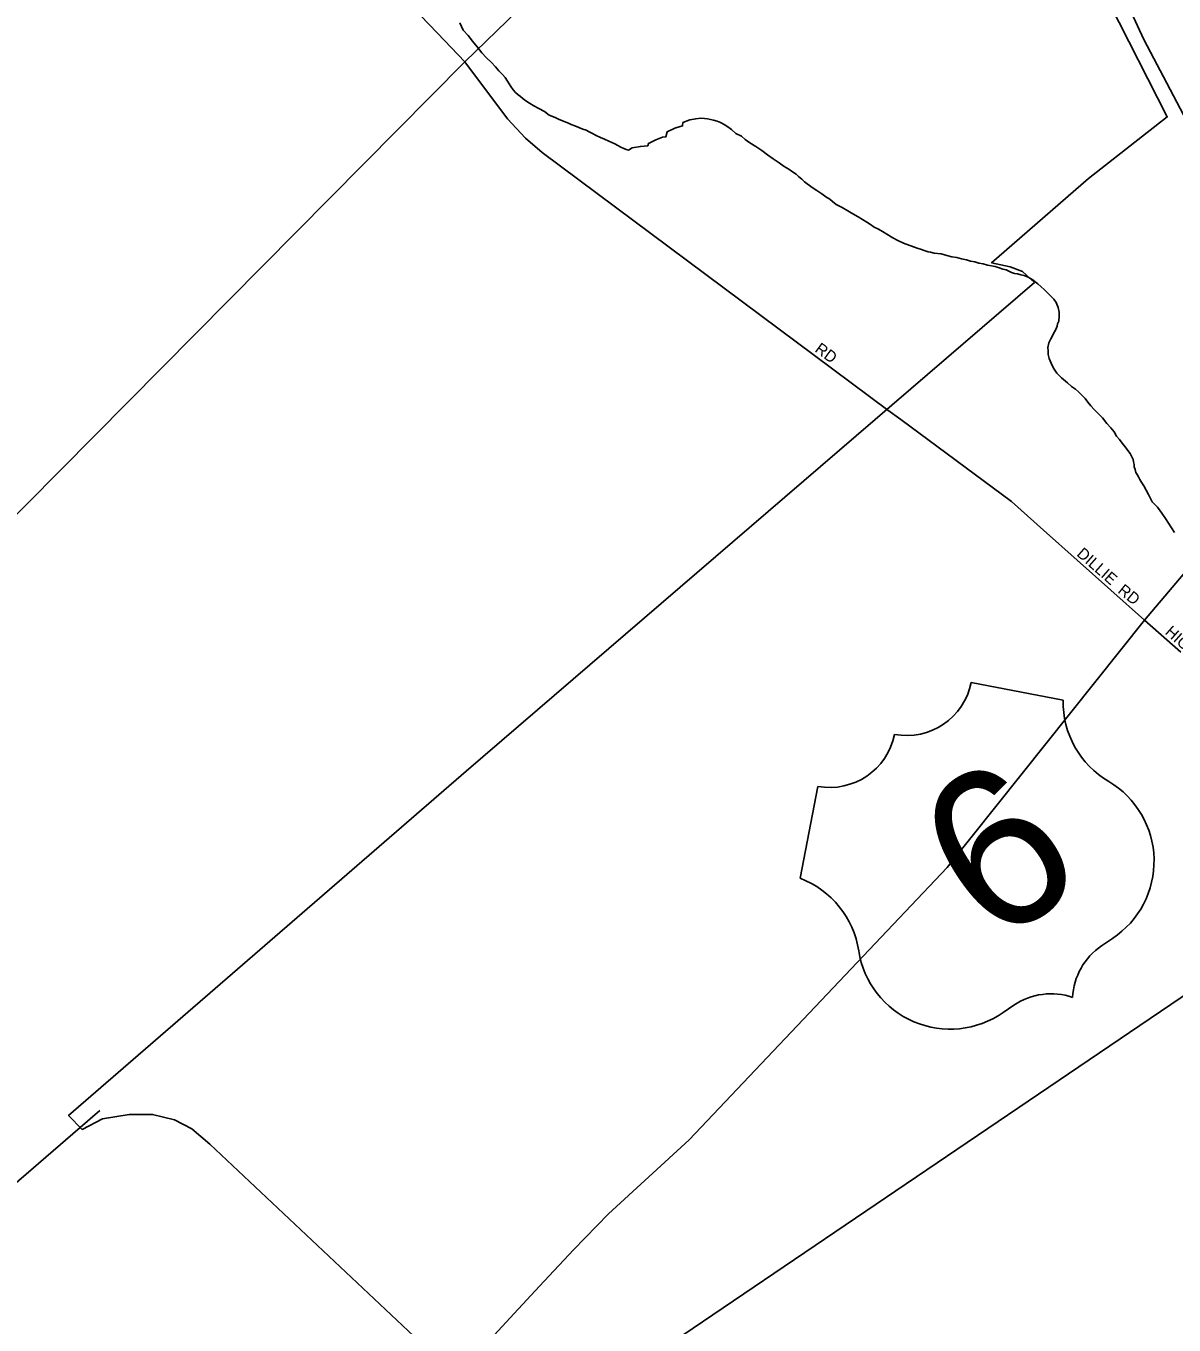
# Model space of a CAD drawing. Extents: x 2139079 to 2262683, y 1235796 to 1334992.
# Drawn here: x 2227269 to 2232304, y 1297941 to 1303635 of the extents above; entities that cross this region are included whole.
import ezdxf

# ---------------------------------------------------------------- set-up
doc = ezdxf.new("R2010")
doc.units = 0
for name, color, linetype in [('GM_X_City_Street', 7, 'Continuous'), ('GM_X_City_Street_Text', 7, 'Continuous'), ('GM_X_Interstate_Route', 7, 'Continuous'), ('GM_X_Minor_River', 7, 'Continuous'), ('GM_X_Rail_Line', 7, 'Continuous'), ('GM_X_US_Location', 7, 'Continuous'), ('GM_X_US_Route', 7, 'Continuous'), ('GM_X_US_Shield', 7, 'Continuous')]:
    doc.layers.add(name, color=color, linetype=linetype)

msp = doc.modelspace()

# ---------------------------------------------------------------- linework, layer by layer
at = {"layer": 'GM_X_City_Street'}
for points in [[(2229193.8, 1303478.3), (2229473.2, 1303749.8), (2230411, 1304512.8), (2231077.9, 1305045.6)], [(2233088.2, 1301840), (2233073.5, 1301864.9), (2233067.4, 1301875.3), (2232171, 1303576.2), (2232079.2, 1303776.5), (2232018.5, 1303862.8), (2231965.8, 1303917.1), (2231913.1, 1303961.8), (2231842.8, 1304001.7), (2231723.7, 1304043.3), (2231524.1, 1304095.9), (2230915.6, 1304246.1), (2230871.3, 1304269.6)], [(2229073.7, 1303604), (2228926.2, 1303758.5), (2228706.1, 1303984), (2228677, 1304023.6), (2228653.9, 1304065.1), (2228645, 1304093.7), (2228640.1, 1304120.2), (2228638.6, 1304139)], [(2231049, 1301951.7), (2229532.4, 1303081.2), (2229459.8, 1303142.9), (2229380.3, 1303227.8), (2229193.8, 1303478.3), (2229073.7, 1303604)], [(2224021.1, 1298258), (2229193.8, 1303478.3)], [(2231731.9, 1301425.2), (2231591.7, 1301550.4), (2231105.2, 1301909.9), (2231049, 1301951.7)], [(2232174.4, 1301030.1), (2231731.9, 1301425.2)], [(2232174.4, 1301030.1), (2232333.7, 1300890.2)]]:
    msp.add_lwpolyline(points, dxfattribs=at)
at = {"layer": 'GM_X_Interstate_Route'}
for points in [[(2229020.3, 1297845.9), (2228075.8, 1298733.3), (2227997.3, 1298801), (2227920.9, 1298840.7), (2227824.6, 1298864.2), (2227722.5, 1298863.7), (2227604.4, 1298844.9), (2227516.5, 1298798.3), (2227456.1, 1298860.1), (2229200.1, 1300368.7), (2231691.7, 1302511.4), (2231639.3, 1302559.2), (2231585.1, 1302579), (2231504, 1302597.7), (2231928.5, 1302966.8), (2232273.7, 1303236.4), (2232020.4, 1303733.6)], [(2232020.4, 1303733.6), (2232273.7, 1303236.4), (2231928.5, 1302966.8), (2231504, 1302597.7), (2231585.1, 1302579), (2231639.3, 1302559.2), (2231691.7, 1302511.4), (2229200.1, 1300368.7), (2227456.1, 1298860.1), (2227516.5, 1298798.3), (2227604.4, 1298844.9), (2227722.5, 1298863.7), (2227824.6, 1298864.2), (2227920.9, 1298840.7), (2227997.3, 1298801), (2228075.8, 1298733.3), (2229020.3, 1297845.9)], [(2229020.3, 1297845.9), (2228075.8, 1298733.3), (2227997.3, 1298801), (2227920.9, 1298840.7), (2227824.6, 1298864.2), (2227722.5, 1298863.7), (2227604.4, 1298844.9), (2227516.5, 1298798.3), (2227456.1, 1298860.1), (2229200.1, 1300368.7), (2231691.7, 1302511.4), (2231639.3, 1302559.2), (2231585.1, 1302579), (2231504, 1302597.7), (2231928.5, 1302966.8), (2232273.7, 1303236.4), (2232020.4, 1303733.6)]]:
    msp.add_lwpolyline(points, dxfattribs=at)
at = {"layer": 'GM_X_Minor_River'}
for points in [[(2229171.5, 1303648.8), (2229186.2, 1303616.9), (2229208.8, 1303593.2), (2229227.4, 1303569.5), (2229248, 1303543.7), (2229268.6, 1303518), (2229289.1, 1303496.3), (2229309.6, 1303476.6), (2229328.1, 1303456.9), (2229342.5, 1303439.1), (2229358.9, 1303423.3), (2229371.2, 1303409.5), (2229381.6, 1303393.6), (2229396.1, 1303369.8), (2229406.4, 1303355.9), (2229416.7, 1303344.1), (2229427, 1303334.2), (2229437.2, 1303326.4), (2229449.4, 1303316.6), (2229461.7, 1303306.8), (2229477.9, 1303297), (2229496.2, 1303285.3), (2229518.6, 1303273.7), (2229542.9, 1303260.1), (2229563.3, 1303244.4), (2229589.6, 1303234.9), (2229603.9, 1303227.1), (2229636.3, 1303213.7), (2229648.4, 1303209.9), (2229660.6, 1303204.1), (2229676.7, 1303198.4), (2229693, 1303190.7), (2229711.2, 1303183), (2229725.3, 1303179.3), (2229739.5, 1303171.5), (2229753.8, 1303163.8), (2229770, 1303156), (2229788.2, 1303146.3), (2229806.5, 1303138.6), (2229824.7, 1303131), (2229838.9, 1303125.2), (2229851, 1303119.4), (2229865.3, 1303111.6), (2229877.5, 1303103.8), (2229891.6, 1303098.1), (2229901.8, 1303094.3), (2229911.9, 1303090.5), (2229927.7, 1303100.8), (2229963.7, 1303107.5), (2229995.8, 1303110.2), (2229999.6, 1303120.3), (2230031.4, 1303137), (2230061.3, 1303147.6), (2230075.3, 1303149.9), (2230080.9, 1303172.1), (2230114.7, 1303186.8), (2230138.6, 1303195.3), (2230148.6, 1303197.5), (2230150.4, 1303211.6), (2230180.2, 1303224.2), (2230206.2, 1303228.8), (2230228.3, 1303231.2), (2230244.4, 1303229.5), (2230258.5, 1303227.8), (2230270.5, 1303226)], [(2230270.5, 1303226), (2230284.7, 1303222.3), (2230300.8, 1303218.6), (2230315, 1303212.8), (2230331.3, 1303203.1), (2230347.5, 1303193.3), (2230363.8, 1303181.6), (2230382.3, 1303163.9), (2230406.6, 1303152.3), (2230422.9, 1303138.5), (2230443.3, 1303122.9), (2230469.8, 1303107.3), (2230496.2, 1303089.7), (2230520.7, 1303070.1), (2230545.2, 1303052.5), (2230571.6, 1303034.9), (2230594.1, 1303019.3), (2230614.4, 1303007.6), (2230630.7, 1302995.9), (2230646.9, 1302986.1), (2230657.2, 1302976.3), (2230671.5, 1302964.5), (2230683.8, 1302952.7), (2230716.4, 1302927.2), (2230736.8, 1302913.6), (2230759.1, 1302899.9), (2230777.5, 1302886.2), (2230793.8, 1302876.5), (2230806, 1302866.7), (2230822.4, 1302852.9), (2230848.7, 1302839.4), (2230873.1, 1302825.8), (2230895.5, 1302812.1), (2230917.9, 1302798.5), (2230938.2, 1302786.8), (2230956.5, 1302775.1), (2230972.7, 1302765.4), (2230989, 1302753.7), (2231007.3, 1302744), (2231025.6, 1302734.3), (2231043.9, 1302722.6), (2231070.3, 1302707), (2231092.7, 1302695.4), (2231117, 1302683.8), (2231177.7, 1302660.9), (2231195.9, 1302655.2), (2231208, 1302651.4), (2231226.2, 1302645.8), (2231236.3, 1302643.9), (2231252.4, 1302640.2), (2231282.6, 1302636.8), (2231306.9, 1302629.2), (2231329.1, 1302623.6), (2231351.2, 1302620), (2231371.4, 1302614.4), (2231393.6, 1302610.8), (2231411.8, 1302605.1), (2231429.9, 1302601.5), (2231448.1, 1302595.8), (2231466.3, 1302592.1), (2231486.4, 1302586.5), (2231518.7, 1302581.1), (2231536.9, 1302575.4), (2231553.1, 1302569.7), (2231567.2, 1302566), (2231579.4, 1302560.2), (2231591.5, 1302554.4), (2231603.6, 1302550.6), (2231617.7, 1302548.8), (2231631.9, 1302545.1), (2231646, 1302541.4), (2231664.2, 1302533.7), (2231674.4, 1302527.8), (2231684.6, 1302522), (2231694.8, 1302514.2), (2231707, 1302504.4), (2231721.3, 1302492.6), (2231733.6, 1302480.8), (2231747.9, 1302467), (2231762.3, 1302453.2), (2231776.6, 1302437.4), (2231787, 1302423.5), (2231795.5, 1302401.6), (2231799.9, 1302381.6), (2231800.2, 1302363.5), (2231798.7, 1302341.4), (2231792.9, 1302329.2), (2231791.1, 1302319.1), (2231785.4, 1302304.9), (2231779.6, 1302294.8), (2231764.1, 1302264.3), (2231754.5, 1302246.1), (2231750.9, 1302225.9), (2231751.1, 1302211.8), (2231751.5, 1302195.8), (2231755.9, 1302177.8), (2231764.3, 1302157.8), (2231774.8, 1302135.9), (2231789.3, 1302114.1), (2231809.8, 1302092.4), (2231836.4, 1302070.8)], [(2231836.4, 1302070.8), (2231854.8, 1302055.1), (2231871.1, 1302043.4), (2231885.4, 1302031.6), (2231899.7, 1302017.8), (2231914.1, 1302002), (2231926.4, 1301986.2), (2231938.8, 1301970.3), (2231953.2, 1301954.5), (2231971.6, 1301936.8), (2231990.1, 1301917.1), (2232008.7, 1301893.3), (2232027.1, 1301873.6), (2232041.6, 1301855.8), (2232052, 1301837.9), (2232064.3, 1301822.1), (2232076.7, 1301806.2), (2232089.1, 1301790.4), (2232101.5, 1301774.5), (2232111.8, 1301760.7), (2232118.1, 1301746.7), (2232124.4, 1301734.8), (2232126.6, 1301724.8), (2232128.8, 1301712.8), (2232129, 1301702.7), (2232133.3, 1301690.8), (2232135.5, 1301678.7), (2232141.8, 1301668.8), (2232148, 1301658.9), (2232154.3, 1301646.9), (2232162.6, 1301633.1), (2232170.9, 1301619.1), (2232181.3, 1301601.3), (2232191.8, 1301581.4), (2232208.5, 1301549.5), (2232231, 1301525.9), (2232249.7, 1301500.1), (2232266.2, 1301476.3), (2232305.6, 1301414.8)]]:
    msp.add_lwpolyline(points, dxfattribs=at)
at = {"layer": 'GM_X_Rail_Line'}
msp.add_lwpolyline([(2227150.4, 1298500.1), (2227593.2, 1298881.4)], dxfattribs=at)
at = {"layer": 'GM_X_US_Route'}
msp.add_lwpolyline([(2202867.6, 1295541.4), (2210353.6, 1284489.3), (2249318.3, 1310881.6), (2241832.3, 1321933.6)], close=True, dxfattribs=at)
msp.add_lwpolyline([(2229183, 1297752.5), (2229251.9, 1297820.1), (2229410.7, 1297992.1), (2229521.9, 1298111.3), (2229670.9, 1298270.9), (2229823.9, 1298428.5), (2230178.2, 1298753.5), (2231308.8, 1299946.9), (2232174.4, 1301030.1), (2232585.7, 1301517.7)], dxfattribs=at)
at = {"layer": 'GM_X_US_Shield'}
for p, q in [((2231817.2, 1300680.1), (2231414.4, 1300757.6)), ((2230742, 1300302.1), (2230664.6, 1299899.3)), ((2231986, 1299603.4), (2232034.1, 1299635.9)), ((2231553.8, 1299310.6), (2231601.8, 1299343.1))]:
    msp.add_line(p, q, dxfattribs=at)
for centre, radius, start, end in [((2231130.2, 1300815.2), 290, 259.6844, 348.5384), ((2232223.2, 1300673.8), 406.1, 179.1105, 239.5643), ((2230794, 1300587.5), 290, 259.6844, 348.5384), ((2231810.1, 1299974.6), 406.1, 303.4731, 59.2795), ((2230519.8, 1299520), 406.1, 8.6585, 69.1123), ((2232148.7, 1299363.2), 290, 124.1114, 177.2415), ((2231322.3, 1299644.2), 406.1, 188.9433, 304.7497), ((2231764.5, 1299103), 290, 70.9813, 124.1114)]:
    msp.add_arc(centre, radius, start, end, dxfattribs=at)

# ---------------------------------------------------------------- texts
at = {"layer": 'GM_X_City_Street_Text'}
for s, rotation, p in [('RD', 323.7506, (2230724.9, 1302210.6)), ('DILLIE', 318.6896, (2231873.5, 1301316.4)), ('RD', 321.3366, (2232053.6, 1301153.9)), ('HIGHLAND', 318.3667, (2232261.2, 1300973.7))]:
    msp.add_text(s, height=50, rotation=rotation, dxfattribs=at).set_placement(p)
at = {"layer": 'GM_X_US_Location'}
for s in ['0', '/']:
    msp.add_text(s, height=1, dxfattribs=at).set_placement((2231625.4, 1300334.7))
msp.add_text('6', height=1, rotation=0, dxfattribs=at).set_placement((2231524.5, 1300127.7))
at = {"layer": 'GM_X_US_Shield'}
msp.add_text('6', height=696.1, rotation=34.1114, dxfattribs=at).set_placement((2231508.3, 1299595))

doc.saveas('drawing.dxf')
